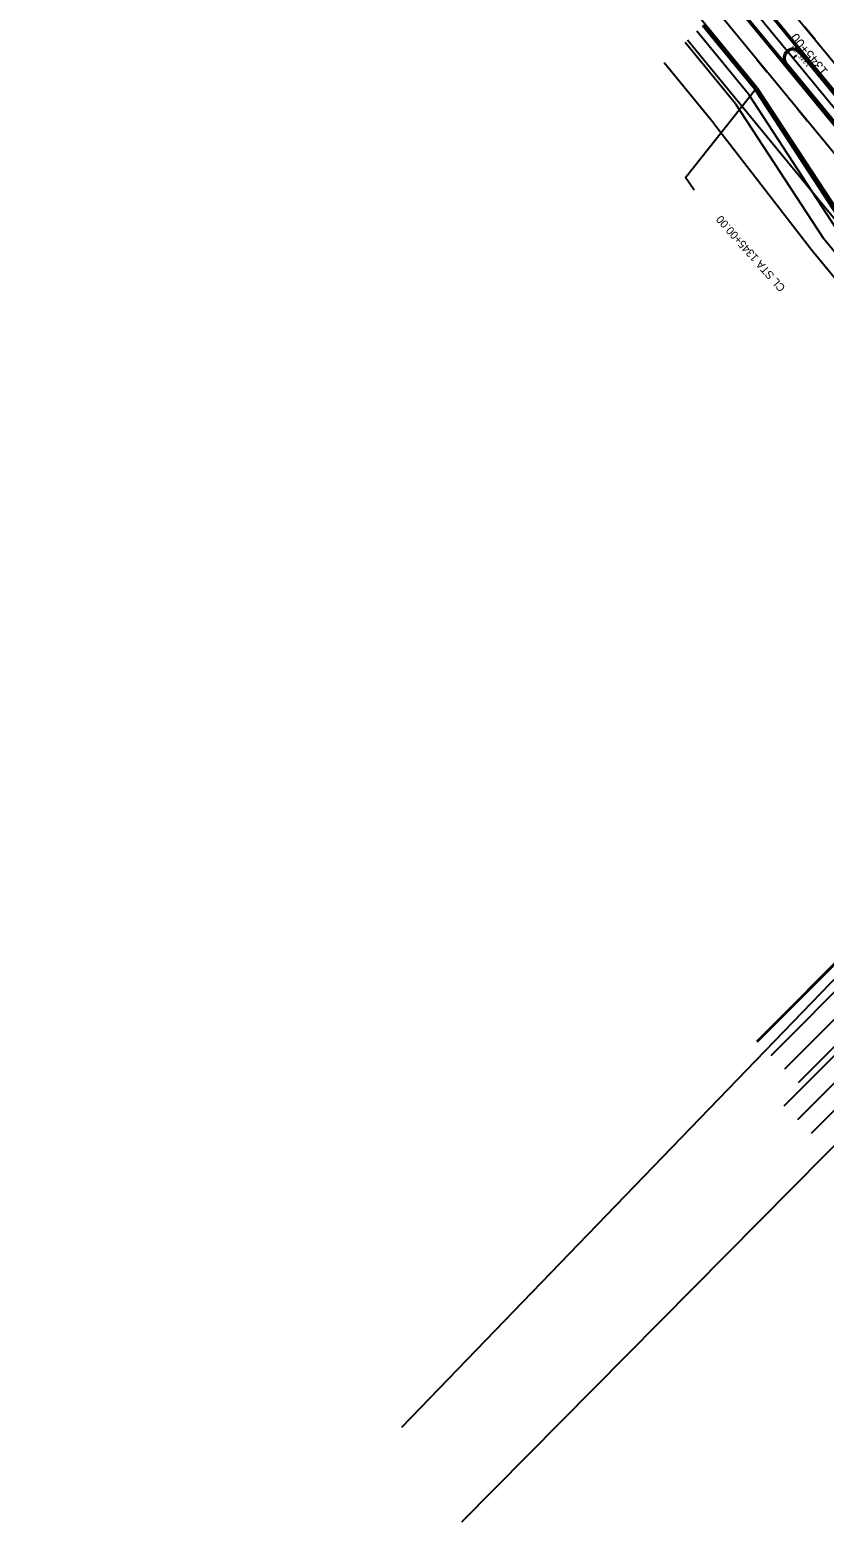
# Model space of a CAD drawing. Extents: x 2252205 to 2259955, y 13788514 to 13798103.
# Drawn here: x 2255600 to 2256096, y 13791710 to 13792642 of the extents above; entities that cross this region are included whole.
import ezdxf

# ---------------------------------------------------------------- set-up
doc = ezdxf.new("R2010")
doc.units = 0
for name, color, linetype in [('GEOM_CENTERLINE_ALIGN', 7, 'Continuous'), ('GEOM_CENTERLINE_STA_100', 7, 'Continuous'), ('GEOM_CENTERLINE_STA_50', 7, 'Continuous'), ('ROAD_BIKE_SHARED_USE', 7, 'Continuous'), ('Road_Curb_Back', 7, 'Continuous'), ('Road_Curb_Face', 7, 'Continuous'), ('Road_EdgeOfPavementInside', 7, 'Continuous'), ('Road_EdgeOfPavementOutside', 7, 'Continuous'), ('ROAD_PAVMRK_Y_4IN_BRK', 7, 'Continuous'), ('ROAD_ROW_EXIST', 7, 'Continuous'), ('ROAD_ROW_PROPOSED', 7, 'Continuous'), ('ROAD_SCRATCH_EP_CONTROL', 7, 'Continuous'), ('ROAD_SCRATCH_PROP_KLEIN_LANES', 7, 'Continuous'), ('TRAF_PAVMRK_W_4IN_BRK', 7, 'Continuous'), ('TRAF_PAVMRK_W_4IN_SLD', 7, 'Continuous'), ('TRAF_PAVMRK_Y_4IN_SLD', 7, 'Continuous')]:
    doc.layers.add(name, color=color, linetype=linetype)

msp = doc.modelspace()

# ---------------------------------------------------------------- linework, layer by layer
at = {"layer": 'GEOM_CENTERLINE_ALIGN'}
msp.add_line((2256266.48, 13792392.92), (2254123.79, 13794999.75), dxfattribs=at)
at = {"layer": 'GEOM_CENTERLINE_STA_100'}
msp.add_line((2256076.4, 13792624.17), (2256078.72, 13792626.08), dxfattribs=at)
at = {"layer": 'GEOM_CENTERLINE_STA_50'}
msp.add_line((2256076.4, 13792624.17), (2256077.56, 13792625.12), dxfattribs=at)
at = {"layer": 'ROAD_BIKE_SHARED_USE'}
for p, q in [((2256040.44, 13792595.74), (2256009.01, 13792633.98)), ((2256048.52, 13792601.66), (2256016.21, 13792640.98)), ((2256048.52, 13792601.66), (2256103.52, 13792517.43)), ((2256040.44, 13792595.74), (2256095.45, 13792511.5)), ((2256222.57, 13792356.84), (2256095.45, 13792511.5))]:
    msp.add_line(p, q, dxfattribs=at)
at = {"layer": 'Road_Curb_Back'}
for p, q in [((2256052.56, 13792604.63), (2256019.8, 13792644.47)), ((2256270.47, 13792396.2), (2256080.4, 13792627.45)), ((2256119.93, 13792563.07), (2256072.41, 13792620.89)), ((2256052.56, 13792604.63), (2256107.56, 13792520.39))]:
    msp.add_line(p, q, dxfattribs=at)
msp.add_arc((2256076.4, 13792624.17), 5.17, 39.41855, 219.41855, dxfattribs=at)
at = {"layer": 'Road_Curb_Face'}
for q in [(2256020.4, 13792645.06), (2256108.23, 13792520.88)]:
    msp.add_line((2256053.23, 13792605.12), q, dxfattribs=at)
at = {"layer": 'Road_EdgeOfPavementInside'}
for p, q in [((2256271.11, 13792396.73), (2256081.04, 13792627.98)), ((2256119.39, 13792562.42), (2256071.77, 13792620.36))]:
    msp.add_line(p, q, dxfattribs=at)
msp.add_arc((2256076.4, 13792624.17), 6, 39.41855, 219.41855, dxfattribs=at)
at = {"layer": 'Road_EdgeOfPavementOutside'}
for p, q in [((2256053.23, 13792605.12), (2256020.4, 13792645.06)), ((2256108.23, 13792520.88), (2256053.23, 13792605.12))]:
    msp.add_line(p, q, dxfattribs=at)
at = {"layer": 'ROAD_PAVMRK_Y_4IN_BRK'}
for p, q in [((2256081.04, 13792627.98), (2256043.33, 13792673.86)), ((2256071.77, 13792620.36), (2256034.07, 13792666.22))]:
    msp.add_line(p, q, dxfattribs=at)
for points in [[(2256081.04, 13792627.98), (2256074.69, 13792635.71)], [(2256071.77, 13792620.36), (2256065.42, 13792628.09)]]:
    msp.add_lwpolyline(points, dxfattribs=at)
at = {"layer": 'ROAD_ROW_EXIST'}
for p, q in [((2256265.67, 13792324.77), (2256010.41, 13792635.34)), ((2256260.79, 13792213.5), (2255831.84, 13791768.87)), ((2256213.9, 13792058.02), (2255869.37, 13791709.71))]:
    msp.add_line(p, q, dxfattribs=at)
at = {"layer": 'ROAD_ROW_PROPOSED'}
for p, q in [((2256027.21, 13792583.23), (2255995.94, 13792621.28)), ((2256027.21, 13792583.23), (2256088.39, 13792504.08)), ((2256088.39, 13792504.08), (2256214.83, 13792350.25))]:
    msp.add_line(p, q, dxfattribs=at)
at = {"layer": 'ROAD_SCRATCH_EP_CONTROL'}
msp.add_lwpolyline([(2256014.66, 13792541.75), (2256009.3, 13792549.59), (2256053.23, 13792605.12)], dxfattribs=at)
at = {"layer": 'ROAD_SCRATCH_PROP_KLEIN_LANES'}
for p, q in [((2256343, 13792300.81), (2256053.56, 13792009.99)), ((2256343.43, 13792300.3), (2256054.04, 13792009.52)), ((2256351.18, 13792291.07), (2256062.54, 13792001.05)), ((2256358.94, 13792281.86), (2256071.05, 13791992.59)), ((2256369.31, 13792269.59), (2256070.61, 13791969.47)), ((2256366.71, 13792272.66), (2256079.56, 13791984.12)), ((2256377.09, 13792260.4), (2256079.12, 13791961)), ((2256384.88, 13792251.22), (2256087.62, 13791952.54))]:
    msp.add_line(p, q, dxfattribs=at)
at = {"layer": 'TRAF_PAVMRK_W_4IN_BRK'}
for p, q in [((2256052.59, 13792681.49), (2256280.38, 13792404.35)), ((2256252.57, 13792381.49), (2256024.81, 13792658.59))]:
    msp.add_line(p, q, dxfattribs=at)
for points in [[(2256090.15, 13792635.8), (2256083.8, 13792643.52)], [(2256090.15, 13792635.79), (2256090.15, 13792635.8)], [(2256053.73, 13792623.4), (2256053.74, 13792623.4)], [(2256053.74, 13792623.4), (2256060.09, 13792615.67)], [(2256079.14, 13792592.49), (2256079.15, 13792592.49)], [(2256079.15, 13792592.49), (2256085.5, 13792584.76)]]:
    msp.add_lwpolyline(points, dxfattribs=at)
at = {"layer": 'TRAF_PAVMRK_W_4IN_SLD'}
for q in [(2256016.32, 13792651.59), (2256109.04, 13792521.48)]:
    msp.add_line((2256054.04, 13792605.71), q, dxfattribs=at)
at = {"layer": 'TRAF_PAVMRK_Y_4IN_SLD'}
for p, q in [((2256271.88, 13792397.37), (2256044.1, 13792674.49)), ((2256118.74, 13792561.64), (2256033.3, 13792665.59))]:
    msp.add_line(p, q, dxfattribs=at)

# ---------------------------------------------------------------- texts
at = {"layer": 'GEOM_CENTERLINE_STA_100'}
msp.add_text('1345+00', height=6, rotation=129.41855, dxfattribs=at).set_placement((2256098.59, 13792616.07))
at = {"layer": 'GEOM_CENTERLINE_STA_50'}
msp.add_text('1345+00', height=3, rotation=129.41855, dxfattribs=at).set_placement((2256087.5, 13792620.12))
at = {"layer": 'ROAD_SCRATCH_EP_CONTROL'}
msp.add_text('CL STA 1345+00.00', height=5, rotation=131.57831, dxfattribs=at).set_placement((2256071.94, 13792480.96))

doc.saveas('drawing.dxf')
